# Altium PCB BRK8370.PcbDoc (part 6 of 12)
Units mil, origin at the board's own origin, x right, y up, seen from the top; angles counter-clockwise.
Board outline 8267.72 x 5708.66 mil, 6 copper layers (L1-TOP, L2-GND, L3-PWR, L4-PWR, L5-GND, L6-BOT), stack 68.606 mil thick; 319 components, 516 nets, 2008 pads, 1743 vias.
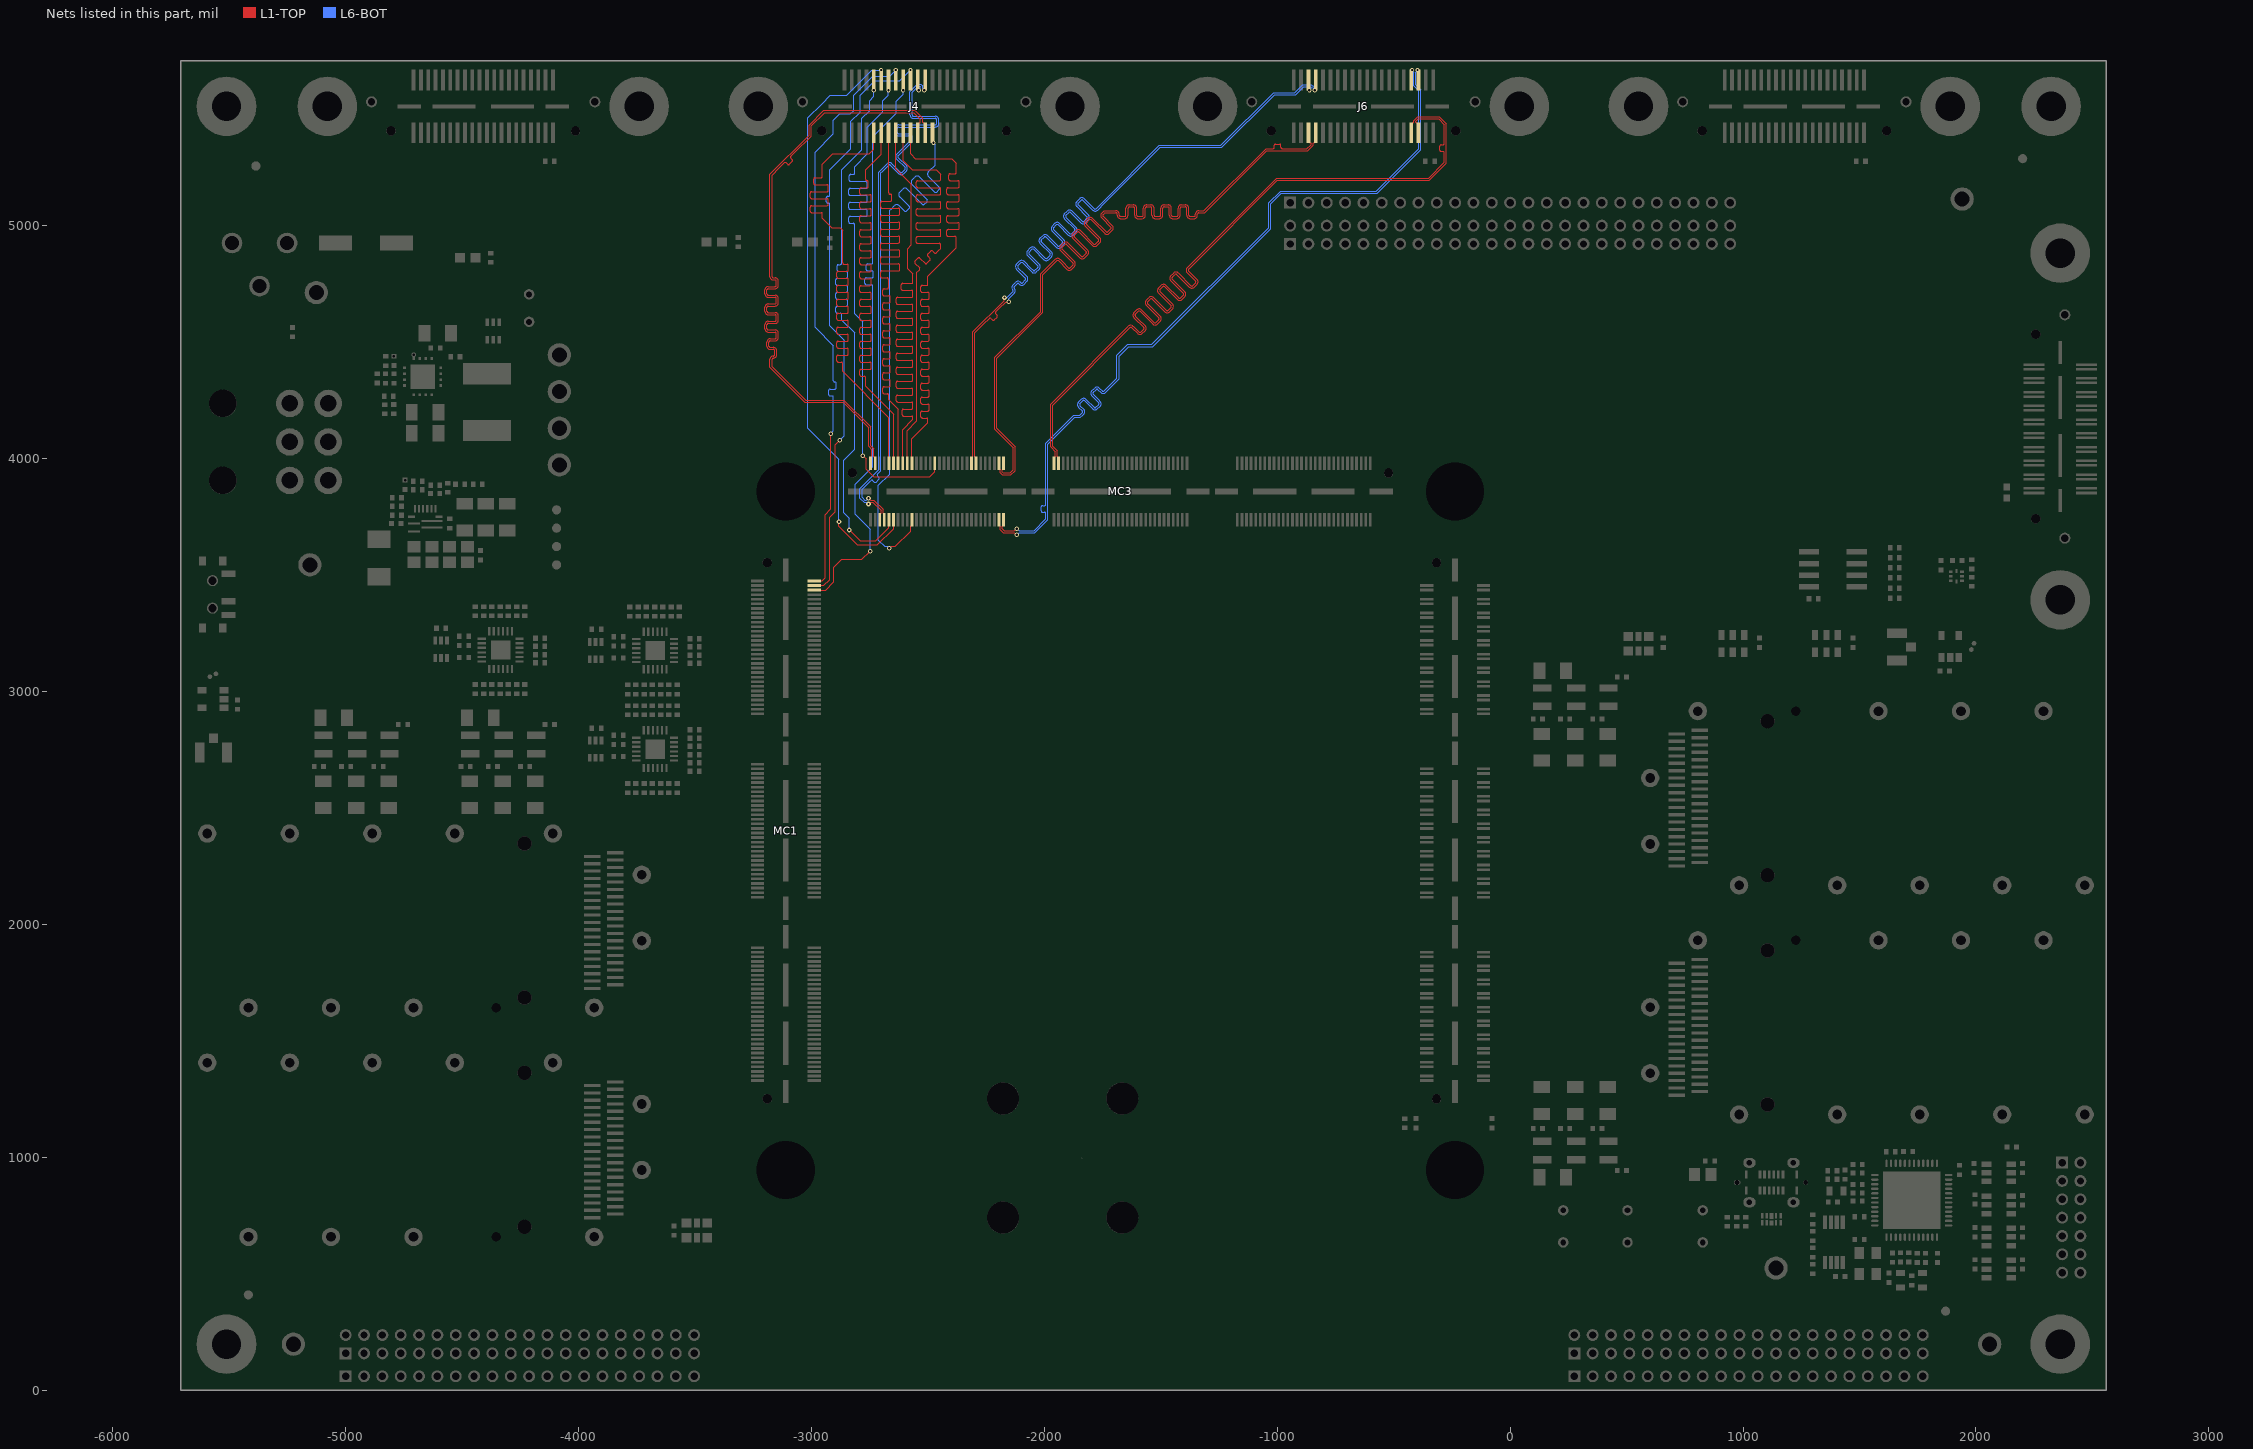
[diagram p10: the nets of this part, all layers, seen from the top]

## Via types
v1: diameter 20, hole 10, L1-TOP to L6-BOT, tented both sides, 957 vias
v2: diameter 18, hole 10, L1-TOP to L6-BOT, tented both sides, 786 vias

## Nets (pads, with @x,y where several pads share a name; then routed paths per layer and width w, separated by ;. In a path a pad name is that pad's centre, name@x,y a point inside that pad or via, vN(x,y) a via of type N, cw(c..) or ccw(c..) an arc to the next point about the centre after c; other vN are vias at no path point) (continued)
PORTB_S11_D5_N: J4.16 MC3.20 | length 2544.6
  L1-TOP w3.3: v1(-2665.35,3614.17) -2663.07,3614.17 -2655.07,3622.17 -2639.71,3622.17 -2574.24,3687.64 -2574.24,3708.63 -2568.9,3713.98 MC3.20@-2568.9,3736.61
  L6-BOT w3.3: v1(-2665.35,3614.17) -2667.64,3614.17 -2675.64,3622.17 -2686.15,3622.17 -2712.65,3648.68 -2712.65,3884.18 -2664.23,3932.6 -2664.23,5065.03 -2655.97,5073.29 -2643.89,5085.37 cw(c-2633.52,5075.01) -2623.16,5085.37 -2600.07,5062.29 ccw(c-2596.07,5066.29) -2592.07,5062.29 -2580.06,5074.3 ccw(c-2584.06,5078.3) -2580.06,5082.3 -2620.8,5123.04 cw(c-2610.46,5133.43) -2620.82,5143.8 -2608.78,5155.84 cw(c-2598.45,5145.44) -2589.6,5157.12 -2589.4,5157.12 -2523.63,5091.35 ccw(c-2519.64,5095.36) -2515.64,5091.36 -2503.63,5103.36 ccw(c-2507.63,5107.37) -2503.64,5111.38 ; -2503.66,5111.4 -2568.04,5175.78 cw(c-2557.71,5186.18) -2568.07,5196.55 -2556.03,5208.59 cw(c-2545.7,5198.19) -2536.85,5209.87 -2536.65,5209.87 -2470.88,5144.1 ccw(c-2466.89,5148.11) -2462.88,5144.11 -2450.88,5156.11 ccw(c-2454.88,5160.12) -2450.89,5164.13 ; v2(-2476.14,5355.65) -2476.14,5353.41 -2469.11,5346.37 -2469.11,5260.16 -2493.3,5235.97 -2497.65,5231.62 ccw(c-2487.28,5221.25) -2497.65,5210.89 -2450.91,5164.15
PORTB_S12_D6_P: J4.17 MC3.6 | length 2544.6
  L1-TOP w3.3: v1(-2754.97,3804.45) -2752.69,3804.45 -2744.69,3812.45 -2736.06,3812.45 -2701.35,3777.74 -2701.35,3764.59 -2706.69,3759.25 MC3.6@-2706.69,3736.61
  L6-BOT w3.3: v1(-2754.97,3804.45) -2757.26,3804.45 -2765.26,3812.45 -2774.25,3812.45 -2791.98,3830.19 -2791.98,3870.64 -2710.91,3951.71 -2710.91,5230.03 -2700.79,5240.16 -2675.23,5265.72 cw(c-2664.86,5255.35) -2654.49,5265.72 -2618.35,5229.58 ccw(c-2614.35,5233.58) -2610.35,5229.58 -2598.34,5241.58 ccw(c-2602.34,5245.58) -2598.34,5249.59 -2634.48,5285.73 cw(c-2624.12,5296.1) -2634.48,5306.46 -2630.13,5310.81 -2580.1,5360.84 -2577.05,5363.89 -2577.05,5380.4 ccw(c-2582.71,5380.4) -2582.71,5386.06 -2626.23,5386.06 cw(c-2626.23,5400.72) -2640.89,5400.72 -2640.89,5417.7 cw(c-2626.23,5417.7) -2626.23,5432.36 -2468.21,5432.36 ccw(c-2468.21,5438.02) -2462.55,5438.02 -2462.55,5455 ccw(c-2468.21,5455) -2468.21,5460.66 -2562.39,5460.66 cw(c-2562.39,5475.32) -2577.05,5475.32 -2577.05,5481.47 -2577.05,5575.8 -2545.57,5607.28 -2530.31,5607.28 -2523.11,5600.08 -2523.11,5590.54 -2516.07,5583.5 v2(-2516.07,5581.25)
PORTB_S13_D7_P: J4.18 MC3.1 | length 2726.1
  L1-TOP w3.3: MC3.1@-2746.06,3979.92 -2746.06,4002.56 -2740.72,4007.9 -2740.72,4037.59 -2754.95,4051.82 -2754.95,4131.96 -2864.37,4241.39 -3028.79,4241.39 -3177.17,4389.76 -3178.29,4390.89 -3178.29,4425.23 cw(c-3163.63,4425.23) -3163.63,4439.89 ccw(c-3163.63,4445.55) -3157.97,4445.55 -3157.97,4462.53 ccw(c-3163.63,4462.53) -3163.63,4468.19 -3176.83,4468.19 cw(c-3176.83,4482.85) -3191.49,4482.85 -3191.49,4499.83 cw(c-3176.83,4499.83) -3176.83,4514.49 -3156.51,4514.49 ccw(c-3156.51,4520.15) -3150.85,4520.15 -3150.85,4537.13 ccw(c-3156.51,4537.13) -3156.51,4542.79 -3185.39,4542.79 cw(c-3185.39,4557.45) -3200.05,4557.45 -3200.05,4574.43 cw(c-3185.39,4574.43) -3185.39,4589.09 -3156.51,4589.09 ccw(c-3156.51,4594.75) -3150.85,4594.75 -3150.85,4611.73 ccw(c-3156.51,4611.73) -3156.51,4617.39 -3185.39,4617.39 cw(c-3185.39,4632.05) -3200.05,4632.05 -3200.05,4649.03 cw(c-3185.39,4649.03) -3185.39,4663.69 -3156.51,4663.69 ccw(c-3156.51,4669.35) -3150.85,4669.35 -3150.85,4686.33 ccw(c-3156.51,4686.33) -3156.51,4691.99 -3185.39,4691.99 cw(c-3185.39,4706.65) -3200.05,4706.65 -3200.05,4723.63 cw(c-3185.39,4723.63) -3185.39,4738.29 -3156.51,4738.29 ccw(c-3156.51,4743.95) -3150.85,4743.95 -3150.85,4760.93 ccw(c-3156.51,4760.93) -3156.51,4766.59 -3163.63,4766.59 cw(c-3163.63,4781.25) -3178.29,4781.25 -3178.29,4787.4 -3178.29,5220.26 -3010.12,5388.43 -3010.12,5431.41 -2947.15,5494.38 -2556.5,5494.38 -2523.01,5460.89 -2523.01,5444.04 -2521.07,5442.11 -2518.11,5442.11 -2511.76,5435.76 J4.18@-2511.76,5399.01
PORTB_S14_D6_N: J4.19 MC3.8 | length 2544.6
  L1-TOP w3.3: v1(-2754.97,3829.45) -2752.69,3829.45 -2744.69,3821.45 -2732.33,3821.45 -2692.35,3781.47 -2692.35,3764.59 -2687.01,3759.25 MC3.8@-2687.01,3736.61
  L6-BOT w3.3: v1(-2754.97,3829.45) -2757.26,3829.45 -2765.26,3821.45 -2770.52,3821.45 -2782.98,3833.92 -2782.98,3866.91 -2766.1,3883.79 -2744.93,3904.96 cw(c-2740.92,3900.96) -2736.92,3904.96 -2730.94,3898.98 ccw(c-2726.94,3902.98) -2722.94,3898.98 -2710.93,3910.99 ccw(c-2714.93,3914.99) -2710.93,3918.99 -2716.91,3924.98 cw(c-2712.91,3928.98) -2716.91,3932.98 -2710.87,3939.02 -2701.91,3947.98 -2701.91,5226.3 -2694.42,5233.79 -2668.86,5259.35 cw(c-2664.86,5255.35) -2660.86,5259.35 -2624.71,5223.21 ccw(c-2614.35,5233.58) -2603.98,5223.21 -2591.94,5235.26 ccw(c-2602.34,5245.58) -2591.98,5255.95 -2628.12,5292.09 cw(c-2624.12,5296.1) -2628.12,5300.1 -2623.77,5304.45 -2568.05,5360.16 -2568.05,5360.84 -2568.05,5380.4 ccw(c-2582.71,5380.4) -2582.71,5395.06 -2626.23,5395.06 cw(c-2626.23,5400.72) -2631.89,5400.72 -2631.89,5417.7 cw(c-2626.23,5417.7) -2626.23,5423.36 -2468.21,5423.36 ccw(c-2468.21,5438.02) -2453.55,5438.02 -2453.55,5455 ccw(c-2468.21,5455) -2468.21,5469.66 -2562.39,5469.66 cw(c-2562.39,5475.32) -2568.05,5475.32 -2568.05,5481.47 -2568.05,5572.07 -2541.84,5598.28 -2534.04,5598.28 -2532.11,5596.35 -2532.11,5590.54 -2539.14,5583.5 v2(-2539.14,5581.25)
PORTB_S15_D7_N: J4.20 MC3.3 | length 2726.1
  L1-TOP w3.3: MC3.3@-2726.38,3979.92 -2726.38,4002.56 -2731.72,4007.9 -2731.72,4041.32 -2745.95,4055.54 -2745.95,4135.69 -2860.65,4250.39 -3025.06,4250.39 -3164.44,4389.76 -3169.29,4394.62 -3169.29,4425.23 cw(c-3163.63,4425.23) -3163.63,4430.89 ccw(c-3163.63,4445.55) -3148.97,4445.55 -3148.97,4462.53 ccw(c-3163.63,4462.53) -3163.63,4477.19 -3176.83,4477.19 cw(c-3176.83,4482.85) -3182.49,4482.85 -3182.49,4499.83 cw(c-3176.83,4499.83) -3176.83,4505.49 -3156.51,4505.49 ccw(c-3156.51,4520.15) -3141.85,4520.15 -3141.85,4537.13 ccw(c-3156.51,4537.13) -3156.51,4551.79 -3185.39,4551.79 cw(c-3185.39,4557.45) -3191.05,4557.45 -3191.05,4574.43 cw(c-3185.39,4574.43) -3185.39,4580.09 -3156.51,4580.09 ccw(c-3156.51,4594.75) -3141.85,4594.75 -3141.85,4611.73 ccw(c-3156.51,4611.73) -3156.51,4626.39 -3185.39,4626.39 cw(c-3185.39,4632.05) -3191.05,4632.05 -3191.05,4649.03 cw(c-3185.39,4649.03) -3185.39,4654.69 -3156.51,4654.69 ccw(c-3156.51,4669.35) -3141.85,4669.35 -3141.85,4686.33 ccw(c-3156.51,4686.33) -3156.51,4700.99 -3185.39,4700.99 cw(c-3185.39,4706.65) -3191.05,4706.65 -3191.05,4723.63 cw(c-3185.39,4723.63) -3185.39,4729.29 -3156.51,4729.29 ccw(c-3156.51,4743.95) -3141.85,4743.95 -3141.85,4760.93 ccw(c-3156.51,4760.93) -3156.51,4775.59 -3163.63,4775.59 cw(c-3163.63,4781.25) -3169.29,4781.25 -3169.29,4787.4 -3169.29,5216.54 -3137.8,5248.03 -3116.62,5269.21 cw(c-3112.62,5265.21) -3108.61,5269.21 -3102.64,5263.23 ccw(c-3098.64,5267.24) -3094.63,5263.23 -3082.63,5275.24 ccw(c-3086.63,5279.24) -3082.63,5283.25 -3088.6,5289.22 cw(c-3084.6,5293.22) -3088.6,5297.23 -3070.85,5314.98 -3001.12,5384.7 -3001.12,5427.68 -2943.43,5485.38 -2560.22,5485.38 -2532.01,5457.16 -2532.01,5444.04 -2533.94,5442.11 -2536.91,5442.11 -2543.26,5435.76 J4.20@-2543.26,5399.01
PORTB_S16: J4.21 MC1.178 | length 2543.1
  L1-TOP w4.96: MC1.178@-2988.58,3454.72 -2946.33,3454.72 -2921.18,3479.87 -2921.18,3747.91 -2897.64,3771.45 -2897.64,4059.06 v1(-2877.95,4078.74)
  L6-BOT w4.96: v1(-2877.95,4078.74) -2858.27,4098.43 -2858.27,4507.87 -2921.26,4570.87 -2921.26,5087.86 -2921.26,5090.34 ccw(c-2927.25,5090.34) -2927.25,5096.33 -2929.69,5096.33 cw(c-2929.69,5102.32) -2935.68,5102.32 -2935.68,5120.3 cw(c-2929.69,5120.3) -2929.69,5126.29 -2927.25,5126.29 ccw(c-2927.25,5132.29) -2921.26,5132.29 -2921.26,5213.47 -2921.26,5240.16 -2853.35,5308.07 -2830.71,5330.71 -2830.71,5448.08 -2791.34,5487.45 -2791.34,5559.06 -2728.35,5622.05 -2620.78,5622.05 v2(-2574.86,5667.97)
PORTB_S17: J4.22 MC3.19 | length 2720.9
  L1-TOP w4.96: J4.22@-2574.76,5399.01 -2574.76,5308.07 -2554.09,5287.4 -2397.64,5287.4 -2377.95,5267.72 -2377.95,5263.07 -2377.95,5229.01 cw(c-2383.95,5229.01) -2383.95,5223.01 -2404.38,5223.01 ccw(c-2404.38,5217.02) -2410.37,5217.02 -2410.37,5199.04 ccw(c-2404.38,5199.04) -2404.38,5193.05 -2371.04,5193.05 cw(c-2371.04,5187.06) -2365.05,5187.06 -2365.05,5169.08 cw(c-2371.04,5169.08) -2371.04,5163.09 -2413.03,5163.09 ccw(c-2413.03,5157.09) -2419.03,5157.09 -2419.03,5139.12 ccw(c-2413.03,5139.12) -2413.03,5133.12 -2371.04,5133.12 cw(c-2371.04,5127.13) -2365.05,5127.13 -2365.05,5109.15 cw(c-2371.04,5109.15) -2371.04,5103.16 -2413.03,5103.16 ccw(c-2413.03,5097.17) -2419.03,5097.17 -2419.03,5079.19 ccw(c-2413.03,5079.19) -2413.03,5073.2 -2371.04,5073.2 cw(c-2371.04,5067.2) -2365.05,5067.2 -2365.05,5049.23 cw(c-2371.04,5049.23) -2371.04,5043.23 -2413.03,5043.23 ccw(c-2413.03,5037.24) -2419.03,5037.24 -2419.03,5019.26 ccw(c-2413.03,5019.26) -2413.03,5013.27 -2371.04,5013.27 cw(c-2371.04,5007.28) -2365.05,5007.28 -2365.05,4989.3 cw(c-2371.04,4989.3) -2371.04,4983.31 -2413.03,4983.31 ccw(c-2413.03,4977.32) -2419.03,4977.32 -2419.03,4959.34 ccw(c-2413.03,4959.34) -2413.03,4953.35 -2383.95,4953.35 cw(c-2383.95,4947.35) -2377.95,4947.35 -2377.95,4944.87 -2377.95,4905.51 -2500,4783.46 -2500,4775.59 -2500,4749.12 cw(c-2505.99,4749.12) -2505.99,4743.13 -2524.29,4743.13 ccw(c-2524.29,4737.13) -2530.28,4737.13 -2530.28,4719.16 ccw(c-2524.29,4719.16) -2524.29,4713.16 -2500.35,4713.16 cw(c-2500.35,4707.17) -2494.36,4707.17 -2494.36,4689.19 cw(c-2500.35,4689.19) -2500.35,4683.2 -2524.29,4683.2 ccw(c-2524.29,4677.21) -2530.28,4677.21 -2530.28,4659.23 ccw(c-2524.29,4659.23) -2524.29,4653.24 -2500.35,4653.24 cw(c-2500.35,4647.24) -2494.36,4647.24 -2494.36,4629.27 cw(c-2500.35,4629.27) -2500.35,4623.27 -2524.29,4623.27 ccw(c-2524.29,4617.28) -2530.28,4617.28 -2530.28,4599.3 ccw(c-2524.29,4599.3) -2524.29,4593.31 -2500.35,4593.31 cw(c-2500.35,4587.32) -2494.36,4587.32 -2494.36,4569.34 cw(c-2500.35,4569.34) -2500.35,4563.35 -2524.29,4563.35 ccw(c-2524.29,4557.36) -2530.28,4557.36 -2530.28,4539.38 ccw(c-2524.29,4539.38) -2524.29,4533.38 -2500.35,4533.38 cw(c-2500.35,4527.39) -2494.36,4527.39 -2494.36,4509.41 cw(c-2500.35,4509.41) -2500.35,4503.42 -2524.29,4503.42 ccw(c-2524.29,4497.43) -2530.28,4497.43 -2530.28,4479.45 ccw(c-2524.29,4479.45) -2524.29,4473.46 -2500.35,4473.46 cw(c-2500.35,4467.47) -2494.36,4467.47 -2494.36,4449.49 cw(c-2500.35,4449.49) -2500.35,4443.5 -2524.29,4443.5 ccw(c-2524.29,4437.5) -2530.28,4437.5 -2530.28,4419.53 ccw(c-2524.29,4419.53) -2524.29,4413.53 -2500.35,4413.53 cw(c-2500.35,4407.54) -2494.36,4407.54 -2494.36,4389.56 cw(c-2500.35,4389.56) -2500.35,4383.57 -2524.29,4383.57 ccw(c-2524.29,4377.58) -2530.28,4377.58 -2530.28,4359.6 ccw(c-2524.29,4359.6) -2524.29,4353.61 -2500.35,4353.61 cw(c-2500.35,4347.61) -2494.36,4347.61 -2494.36,4329.64 cw(c-2500.35,4329.64) -2500.35,4323.64 -2524.29,4323.64 ccw(c-2524.29,4317.65) -2530.28,4317.65 -2530.28,4299.67 ccw(c-2524.29,4299.67) -2524.29,4293.68 -2500.35,4293.68 cw(c-2500.35,4287.69) -2494.36,4287.69 -2494.36,4269.71 cw(c-2500.35,4269.71) -2500.35,4263.72 -2524.29,4263.72 ccw(c-2524.29,4257.73) -2530.28,4257.73 -2530.28,4239.75 ccw(c-2524.29,4239.75) -2524.29,4233.75 -2500.35,4233.75 cw(c-2500.35,4227.76) -2494.36,4227.76 -2494.36,4209.78 cw(c-2500.35,4209.78) -2500.35,4203.79 -2524.29,4203.79 ccw(c-2524.29,4197.8) -2530.28,4197.8 -2530.28,4179.82 ccw(c-2524.29,4179.82) -2524.29,4173.83 -2505.99,4173.83 cw(c-2505.99,4167.84) -2500,4167.84 -2500,4165.35 -2500,4153.54 -2568.9,4084.65 MC3.19@-2568.9,3979.92
PORTB_S18: J4.23 MC1.176 | length 2543.1
  L1-TOP w4.96: MC1.176@-2988.58,3435.04 -2939.64,3435.04 -2904.22,3470.46 -2904.22,3532.79 -2870.08,3566.93 -2783.46,3566.93 v1(-2748.03,3602.36)
  L6-BOT w4.96: v1(-2748.03,3602.36) -2748.03,3696.85 -2811.02,3759.84 -2811.02,3889.76 -2736.22,3964.57 -2736.22,4736.99 -2736.22,4739.47 ccw(c-2742.21,4739.47) -2742.21,4745.47 -2764.43,4745.47 cw(c-2764.43,4751.46) -2770.42,4751.46 -2770.42,4769.44 cw(c-2764.43,4769.44) -2764.43,4775.43 -2740.83,4775.43 ccw(c-2740.83,4781.42) -2734.84,4781.42 -2734.84,4799.4 ccw(c-2740.83,4799.4) -2740.83,4805.39 -2758.42,4805.39 cw(c-2758.42,4811.39) -2764.41,4811.39 -2764.41,4829.36 cw(c-2758.42,4829.36) -2758.42,4835.36 -2742.21,4835.36 ccw(c-2742.21,4841.35) -2736.22,4841.35 -2736.22,4872.32 -2736.22,5381.89 -2635.31,5482.8 -2635.31,5533.98 -2606.36,5562.94 v2(-2606.36,5581.25)
PORTB_S19: J4.24 MC3.17 | length 2720.9
  L1-TOP w4.96: J4.24@-2606.26,5399.01 -2606.26,5279.48 -2566.93,5240.16 -2464.57,5240.16 -2444.88,5220.47 -2444.88,5215.83 -2444.88,5198.9 cw(c-2450.87,5198.9) -2450.87,5192.91 -2543.6,5192.91 ccw(c-2543.6,5186.91) -2549.6,5186.91 -2549.6,5168.94 ccw(c-2543.6,5168.94) -2543.6,5162.94 -2449.93,5162.94 cw(c-2449.93,5156.95) -2443.94,5156.95 -2443.94,5138.97 cw(c-2449.93,5138.97) -2449.93,5132.98 -2543.6,5132.98 ccw(c-2543.6,5126.99) -2549.6,5126.99 -2549.6,5109.01 ccw(c-2543.6,5109.01) -2543.6,5103.02 -2449.93,5103.02 cw(c-2449.93,5097.03) -2443.94,5097.03 -2443.94,5079.05 cw(c-2449.93,5079.05) -2449.93,5073.06 -2543.6,5073.06 ccw(c-2543.6,5067.06) -2549.6,5067.06 -2549.6,5049.09 ccw(c-2543.6,5049.09) -2543.6,5043.09 -2449.93,5043.09 cw(c-2449.93,5037.1) -2443.94,5037.1 -2443.94,5019.12 cw(c-2449.93,5019.12) -2449.93,5013.13 -2543.6,5013.13 ccw(c-2543.6,5007.14) -2549.6,5007.14 -2549.6,4989.16 ccw(c-2543.6,4989.16) -2543.6,4983.17 -2449.93,4983.17 cw(c-2449.93,4977.17) -2443.94,4977.17 -2443.94,4959.2 cw(c-2449.93,4959.2) -2449.93,4953.2 -2543.6,4953.2 ccw(c-2543.6,4947.21) -2549.6,4947.21 -2549.6,4929.23 ccw(c-2543.6,4929.23) -2543.6,4923.24 -2450.87,4923.24 cw(c-2450.87,4917.25) -2444.88,4917.25 -2444.88,4914.77 -2444.88,4901.57 -2451.13,4895.33 -2463.82,4882.63 cw(c-2468.06,4886.87) -2472.3,4882.63 -2480.32,4890.66 ccw(c-2484.56,4886.42) -2488.8,4890.66 -2501.51,4877.94 ccw(c-2497.27,4873.71) -2501.51,4869.47 -2491.28,4859.24 cw(c-2495.52,4855) -2491.28,4850.77 -2503.99,4838.05 cw(c-2508.23,4842.29) -2512.47,4838.05 -2534.44,4860.02 ccw(c-2538.67,4855.78) -2542.91,4860.02 -2555.62,4847.31 ccw(c-2551.39,4843.07) -2555.62,4838.83 -2535.86,4819.07 cw(c-2540.1,4814.83) -2535.86,4810.6 -2537.62,4808.84 -2547.24,4799.21 -2547.24,4161.42 -2588.58,4120.08 MC3.17@-2588.58,3979.92
PORTB_S20: J4.25 MC1.180 | length 2543.1
  L1-TOP w4.96: MC1.180@-2988.58,3474.41 -2954.72,3474.41 -2941.75,3487.39 -2941.75,3759.04 -2917.32,3783.46 v1(-2917.32,4106.3)
  L6-BOT w4.96: v1(-2917.32,4106.3) -2905.51,4118.11 -2905.51,4259.84 -2905.51,4262.32 ccw(c-2911.5,4262.32) -2911.5,4268.32 -2920.42,4268.32 cw(c-2920.42,4274.31) -2926.41,4274.31 -2926.41,4292.29 cw(c-2920.42,4292.29) -2920.42,4298.28 -2899.52,4298.28 ccw(c-2899.52,4304.27) -2893.53,4304.27 -2893.53,4322.25 ccw(c-2899.52,4322.25) -2899.52,4328.24 cw(c-2899.52,4334.24) -2905.51,4334.24 -2905.51,4381.89 -2905.51,4484.25 -2984.25,4562.99 -2984.25,5314.96 -2905.51,5393.7 -2905.51,5452.76 -2877.95,5480.32 -2832.74,5480.32 -2818.9,5494.16 -2818.9,5559.28 -2736.45,5641.73 -2664.09,5641.73 v2(-2637.86,5667.97)
PORTB_S21: J4.26 MC3.15 | length 2720.9
  L1-TOP w4.96: J4.26@-2637.76,5399.01 -2637.76,5244.05 -2570.87,5177.17 -2570.87,4917.32 -2586.61,4901.57 -2586.61,4814.96 -2564.21,4792.55 -2564.21,4784.85 -2564.21,4757.68 cw(c-2570.2,4757.68) -2570.2,4751.69 -2607.81,4751.69 ccw(c-2607.81,4745.7) -2613.8,4745.7 -2613.8,4727.72 ccw(c-2607.81,4727.72) -2607.81,4721.73 -2570.2,4721.73 cw(c-2570.2,4715.73) -2564.21,4715.73 -2564.21,4697.75 cw(c-2570.2,4697.75) -2570.2,4691.76 -2630.16,4691.76 ccw(c-2630.16,4685.77) -2636.16,4685.77 -2636.16,4667.79 ccw(c-2630.16,4667.79) -2630.16,4661.8 -2570.2,4661.8 cw(c-2570.2,4655.81) -2564.21,4655.81 -2564.21,4637.83 cw(c-2570.2,4637.83) -2570.2,4631.84 -2630.16,4631.84 ccw(c-2630.16,4625.84) -2636.16,4625.84 -2636.16,4607.87 ccw(c-2630.16,4607.87) -2630.16,4601.87 -2570.2,4601.87 cw(c-2570.2,4595.88) -2564.21,4595.88 -2564.21,4577.9 cw(c-2570.2,4577.9) -2570.2,4571.91 -2630.16,4571.91 ccw(c-2630.16,4565.92) -2636.16,4565.92 -2636.16,4547.94 ccw(c-2630.16,4547.94) -2630.16,4541.95 -2570.2,4541.95 cw(c-2570.2,4535.95) -2564.21,4535.95 -2564.21,4517.98 cw(c-2570.2,4517.98) -2570.2,4511.98 -2630.16,4511.98 ccw(c-2630.16,4505.99) -2636.16,4505.99 -2636.16,4488.01 ccw(c-2630.16,4488.01) -2630.16,4482.02 -2570.2,4482.02 cw(c-2570.2,4476.03) -2564.21,4476.03 -2564.21,4458.05 cw(c-2570.2,4458.05) -2570.2,4452.06 -2630.16,4452.06 ccw(c-2630.16,4446.07) -2636.16,4446.07 -2636.16,4428.09 ccw(c-2630.16,4428.09) -2630.16,4422.1 -2570.2,4422.1 cw(c-2570.2,4416.1) -2564.21,4416.1 -2564.21,4398.12 cw(c-2570.2,4398.12) -2570.2,4392.13 -2630.16,4392.13 ccw(c-2630.16,4386.14) -2636.16,4386.14 -2636.16,4368.16 ccw(c-2630.16,4368.16) -2630.16,4362.17 -2570.2,4362.17 cw(c-2570.2,4356.18) -2564.21,4356.18 -2564.21,4338.2 cw(c-2570.2,4338.2) -2570.2,4332.21 -2630.16,4332.21 ccw(c-2630.16,4326.21) -2636.16,4326.21 -2636.16,4308.24 ccw(c-2630.16,4308.24) -2630.16,4302.24 -2570.2,4302.24 cw(c-2570.2,4296.25) -2564.21,4296.25 -2564.21,4278.27 cw(c-2570.2,4278.27) -2570.2,4272.28 -2629.66,4272.28 ccw(c-2629.66,4266.29) -2635.65,4266.29 -2635.65,4248.31 ccw(c-2629.66,4248.31) -2629.66,4242.32 -2570.2,4242.32 cw(c-2570.2,4236.32) -2564.21,4236.32 -2564.21,4218.35 cw(c-2570.2,4218.35) -2570.2,4212.35 -2605,4212.35 ccw(c-2605,4206.36) -2610.99,4206.36 -2610.99,4188.38 ccw(c-2605,4188.38) -2605,4182.39 -2570.2,4182.39 cw(c-2570.2,4176.4) -2564.21,4176.4 -2564.21,4173.92 -2564.21,4168.44 -2608.27,4124.38 MC3.15@-2608.27,3979.92
PORTB_S22: J4.27 MC3.29 | length 2543.1
  L1-TOP w4.96: v1(-2779.53,4011.81) -2765.86,3998.14 -2765.86,3954.69 -2732.43,3921.26 -2492.13,3921.26 -2470.47,3942.91 MC3.29@-2470.47,3979.92
  L6-BOT w4.96: v1(-2779.53,4011.81) -2779.53,4586.61 -2814.96,4622.05 -2814.96,5001.31 -2814.96,5003.79 ccw(c-2820.95,5003.79) -2820.95,5009.78 -2833.97,5009.78 cw(c-2833.97,5015.77) -2839.96,5015.77 -2839.96,5033.75 cw(c-2833.97,5033.75) -2833.97,5039.74 -2766.51,5039.74 ccw(c-2766.51,5045.74) -2760.51,5045.74 -2760.51,5063.71 ccw(c-2766.51,5063.71) -2766.51,5069.71 -2833.97,5069.71 cw(c-2833.97,5075.7) -2839.96,5075.7 -2839.96,5093.68 cw(c-2833.97,5093.68) -2833.97,5099.67 -2766.51,5099.67 ccw(c-2766.51,5105.66) -2760.51,5105.66 -2760.51,5123.64 ccw(c-2766.51,5123.64) -2766.51,5129.63 -2833.97,5129.63 cw(c-2833.97,5135.63) -2839.96,5135.63 -2839.96,5153.6 cw(c-2833.97,5153.6) -2833.97,5159.6 -2766.51,5159.6 ccw(c-2766.51,5165.59) -2760.51,5165.59 -2760.51,5183.57 ccw(c-2766.51,5183.57) -2766.51,5189.56 -2831.55,5189.56 cw(c-2831.55,5195.55) -2837.54,5195.55 -2837.54,5213.53 cw(c-2831.55,5213.53) -2831.55,5219.52 -2820.95,5219.52 ccw(c-2820.95,5225.51) -2814.96,5225.51 -2814.96,5243.16 -2814.96,5252.95 -2759.84,5308.07 -2759.84,5421.26 -2692.91,5488.19 -2692.91,5535.2 -2669.36,5558.76 v2(-2669.36,5581.25)
PORTB_S23: J4.28 MC3.13 | length 2720.9
  L1-TOP w4.96: J4.28@-2669.26,5399.01 -2669.26,5171.78 -2669.26,5140.97 ccw(c-2663.26,5140.97) -2663.26,5134.98 -2661.14,5134.98 cw(c-2661.14,5128.99) -2655.14,5128.99 -2655.14,5111.01 cw(c-2661.14,5111.01) -2661.14,5105.02 -2697.52,5105.02 ccw(c-2697.52,5099.03) -2703.51,5099.03 -2703.51,5081.05 ccw(c-2697.52,5081.05) -2697.52,5075.06 -2626.59,5075.06 cw(c-2626.59,5069.06) -2620.6,5069.06 -2620.6,5051.09 cw(c-2626.59,5051.09) -2626.59,5045.09 -2697.52,5045.09 ccw(c-2697.52,5039.1) -2703.51,5039.1 -2703.51,5021.12 ccw(c-2697.52,5021.12) -2697.52,5015.13 -2626.59,5015.13 cw(c-2626.59,5009.14) -2620.6,5009.14 -2620.6,4991.16 cw(c-2626.59,4991.16) -2626.59,4985.17 -2697.52,4985.17 ccw(c-2697.52,4979.17) -2703.51,4979.17 -2703.51,4961.2 ccw(c-2697.52,4961.2) -2697.52,4955.2 -2626.59,4955.2 cw(c-2626.59,4949.21) -2620.6,4949.21 -2620.6,4931.23 cw(c-2626.59,4931.23) -2626.59,4925.24 -2697.52,4925.24 ccw(c-2697.52,4919.25) -2703.51,4919.25 -2703.51,4901.27 ccw(c-2697.52,4901.27) -2697.52,4895.28 -2626.59,4895.28 cw(c-2626.59,4889.28) -2620.6,4889.28 -2620.6,4871.31 cw(c-2626.59,4871.31) -2626.59,4865.31 -2697.52,4865.31 ccw(c-2697.52,4859.32) -2703.51,4859.32 -2703.51,4841.34 ccw(c-2697.52,4841.34) -2697.52,4835.35 -2626.59,4835.35 cw(c-2626.59,4829.36) -2620.6,4829.36 -2620.6,4811.38 cw(c-2626.59,4811.38) -2626.59,4805.39 -2697.52,4805.39 ccw(c-2697.52,4799.4) -2703.51,4799.4 -2703.51,4781.42 ccw(c-2697.52,4781.42) -2697.52,4775.43 -2675.25,4775.43 cw(c-2675.25,4769.43) -2669.26,4769.43 -2669.26,4766.95 -2669.26,4746.64 -2669.26,4734.09 cw(c-2675.25,4734.09) -2675.25,4728.1 -2688.26,4728.1 ccw(c-2688.26,4722.11) -2694.26,4722.11 -2694.26,4704.13 ccw(c-2688.26,4704.13) -2688.26,4698.14 -2667.53,4698.14 cw(c-2667.53,4692.14) -2661.54,4692.14 -2661.54,4674.17 cw(c-2667.53,4674.17) -2667.53,4668.17 -2688.26,4668.17 ccw(c-2688.26,4662.18) -2694.26,4662.18 -2694.26,4644.2 ccw(c-2688.26,4644.2) -2688.26,4638.21 -2667.53,4638.21 cw(c-2667.53,4632.22) -2661.54,4632.22 -2661.54,4614.24 cw(c-2667.53,4614.24) -2667.53,4608.25 -2688.26,4608.25 ccw(c-2688.26,4602.26) -2694.26,4602.26 -2694.26,4584.28 ccw(c-2688.26,4584.28) -2688.26,4578.29 -2667.53,4578.29 cw(c-2667.53,4572.29) -2661.54,4572.29 -2661.54,4554.31 cw(c-2667.53,4554.31) -2667.53,4548.32 -2688.26,4548.32 ccw(c-2688.26,4542.33) -2694.26,4542.33 -2694.26,4524.35 ccw(c-2688.26,4524.35) -2688.26,4518.36 -2667.53,4518.36 cw(c-2667.53,4512.37) -2661.54,4512.37 -2661.54,4494.39 cw(c-2667.53,4494.39) -2667.53,4488.4 -2688.26,4488.4 ccw(c-2688.26,4482.4) -2694.26,4482.4 -2694.26,4464.43 ccw(c-2688.26,4464.43) -2688.26,4458.43 -2667.53,4458.43 cw(c-2667.53,4452.44) -2661.54,4452.44 -2661.54,4434.46 cw(c-2667.53,4434.46) -2667.53,4428.47 -2688.26,4428.47 ccw(c-2688.26,4422.48) -2694.26,4422.48 -2694.26,4404.5 ccw(c-2688.26,4404.5) -2688.26,4398.51 -2667.53,4398.51 cw(c-2667.53,4392.51) -2661.54,4392.51 -2661.54,4374.54 cw(c-2667.53,4374.54) -2667.53,4368.54 -2688.26,4368.54 ccw(c-2688.26,4362.55) -2694.26,4362.55 -2694.26,4344.57 ccw(c-2688.26,4344.57) -2688.26,4338.58 -2667.53,4338.58 cw(c-2667.53,4332.59) -2661.54,4332.59 -2661.54,4314.61 cw(c-2667.53,4314.61) -2667.53,4308.62 -2688.26,4308.62 ccw(c-2688.26,4302.63) -2694.26,4302.63 -2694.26,4284.65 ccw(c-2688.26,4284.65) -2688.26,4278.66 -2675.25,4278.66 cw(c-2675.25,4272.66) -2669.26,4272.66 -2669.26,4270.18 -2669.26,4251.93 -2627.95,4210.63 MC3.13@-2627.95,3979.92
PORTB_S24: J4.29 MC3.12 | length 2542.3
  L1-TOP w4.96: v1(-2881.89,3728.35) -2881.89,3708.66 -2803.15,3629.92 -2716.54,3629.92 -2647.64,3698.82 MC3.12@-2647.64,3736.61
  L6-BOT w4.96: v1(-2881.89,3728.35) -2881.89,3996.06 -3015.75,4129.92 -3015.75,5462.13 -2954.72,5523.15 -2918.82,5559.06 -2848.62,5559.06 -2740.88,5666.8 -2702.03,5666.8 v2(-2700.86,5667.97)
PORTB_S25: J4.30 MC3.11 | length 2720.9
  L1-TOP w4.96: J4.30@-2700.76,5399.01 -2700.76,5307.12 -2767.72,5240.16 -2767.72,5229.08 -2767.72,5198.22 ccw(c-2761.72,5198.22) -2761.72,5192.23 cw(c-2761.72,5186.23) -2755.73,5186.23 -2755.73,5168.26 cw(c-2761.72,5168.26) -2761.72,5162.26 -2786.49,5162.26 ccw(c-2786.49,5156.27) -2792.48,5156.27 -2792.48,5138.29 ccw(c-2786.49,5138.29) -2786.49,5132.3 -2748.71,5132.3 cw(c-2748.71,5126.31) -2742.72,5126.31 -2742.72,5108.33 cw(c-2748.71,5108.33) -2748.71,5102.34 -2786.72,5102.34 ccw(c-2786.72,5096.34) -2792.72,5096.34 -2792.72,5078.37 ccw(c-2786.72,5078.37) -2786.72,5072.37 -2748.71,5072.37 cw(c-2748.71,5066.38) -2742.72,5066.38 -2742.72,5048.4 cw(c-2748.71,5048.4) -2748.71,5042.41 -2786.72,5042.41 ccw(c-2786.72,5036.42) -2792.72,5036.42 -2792.72,5018.44 ccw(c-2786.72,5018.44) -2786.72,5012.45 -2748.71,5012.45 cw(c-2748.71,5006.46) -2742.72,5006.46 -2742.72,4988.48 cw(c-2748.71,4988.48) -2748.71,4982.49 -2786.72,4982.49 ccw(c-2786.72,4976.49) -2792.72,4976.49 -2792.72,4958.51 ccw(c-2786.72,4958.51) -2786.72,4952.52 -2748.71,4952.52 cw(c-2748.71,4946.53) -2742.72,4946.53 -2742.72,4928.55 cw(c-2748.71,4928.55) -2748.71,4922.56 -2786.72,4922.56 ccw(c-2786.72,4916.57) -2792.72,4916.57 -2792.72,4898.59 ccw(c-2786.72,4898.59) -2786.72,4892.6 -2748.71,4892.6 cw(c-2748.71,4886.6) -2742.72,4886.6 -2742.72,4868.63 cw(c-2748.71,4868.63) -2748.71,4862.63 -2786.72,4862.63 ccw(c-2786.72,4856.64) -2792.72,4856.64 -2792.72,4838.66 ccw(c-2786.72,4838.66) -2786.72,4832.67 -2748.71,4832.67 cw(c-2748.71,4826.68) -2742.72,4826.68 -2742.72,4808.7 cw(c-2748.71,4808.7) -2748.71,4802.71 -2786.72,4802.71 ccw(c-2786.72,4796.71) -2792.72,4796.71 -2792.72,4778.74 ccw(c-2786.72,4778.74) -2786.72,4772.74 -2748.71,4772.74 cw(c-2748.71,4766.75) -2742.72,4766.75 -2742.72,4748.77 cw(c-2748.71,4748.77) -2748.71,4742.78 -2786.72,4742.78 ccw(c-2786.72,4736.79) -2792.72,4736.79 -2792.72,4718.81 ccw(c-2786.72,4718.81) -2786.72,4712.82 -2748.71,4712.82 cw(c-2748.71,4706.83) -2742.72,4706.83 -2742.72,4688.85 cw(c-2748.71,4688.85) -2748.71,4682.86 -2786.72,4682.86 ccw(c-2786.72,4676.86) -2792.72,4676.86 -2792.72,4658.88 ccw(c-2786.72,4658.88) -2786.72,4652.89 -2748.71,4652.89 cw(c-2748.71,4646.9) -2742.72,4646.9 -2742.72,4628.92 cw(c-2748.71,4628.92) -2748.71,4622.93 -2786.72,4622.93 ccw(c-2786.72,4616.94) -2792.72,4616.94 -2792.72,4598.96 ccw(c-2786.72,4598.96) -2786.72,4592.97 -2748.71,4592.97 cw(c-2748.71,4586.97) -2742.72,4586.97 -2742.72,4569 cw(c-2748.71,4569) -2748.71,4563 -2786.72,4563 ccw(c-2786.72,4557.01) -2792.72,4557.01 -2792.72,4539.03 ccw(c-2786.72,4539.03) -2786.72,4533.04 -2748.71,4533.04 cw(c-2748.71,4527.05) -2742.72,4527.05 -2742.72,4509.07 cw(c-2748.71,4509.07) -2748.71,4503.08 -2786.72,4503.08 ccw(c-2786.72,4497.08) -2792.72,4497.08 -2792.72,4479.11 ccw(c-2786.72,4479.11) -2786.72,4473.11 -2748.71,4473.11 cw(c-2748.71,4467.12) -2742.72,4467.12 -2742.72,4449.14 cw(c-2748.71,4449.14) -2748.71,4443.15 -2786.72,4443.15 ccw(c-2786.72,4437.16) -2792.72,4437.16 -2792.72,4419.18 ccw(c-2786.72,4419.18) -2786.72,4413.19 -2748.71,4413.19 cw(c-2748.71,4407.2) -2742.72,4407.2 -2742.72,4389.22 cw(c-2748.71,4389.22) -2748.71,4383.23 -2786.72,4383.23 ccw(c-2786.72,4377.23) -2792.72,4377.23 -2792.72,4359.25 ccw(c-2786.72,4359.25) -2786.72,4353.26 -2773.71,4353.26 cw(c-2773.71,4347.27) -2767.72,4347.27 -2767.72,4344.79 -2767.72,4311.02 -2647.64,4190.94 MC3.11@-2647.64,3979.92
PORTB_S26: J4.31 MC3.10 | length 2543.1
  L1-TOP w4.96: v1(-2837.42,3692.69) -2836.69,3692.69 -2790.89,3646.88 -2723.56,3646.88 -2667.32,3703.12 MC3.10@-2667.32,3736.61
  L6-BOT w4.96: v1(-2837.42,3692.69) -2837.42,3742.93 -2862.19,3767.7 -2862.19,3992.14 -2814.96,4039.37 -2814.96,4539.37 -2870.08,4594.49 -2870.08,4614.74 -2870.08,4617.22 ccw(c-2876.07,4617.22) -2876.07,4623.21 -2889.09,4623.21 cw(c-2889.09,4629.2) -2895.08,4629.2 -2895.08,4647.18 cw(c-2889.09,4647.18) -2889.09,4653.17 -2851.07,4653.17 ccw(c-2851.07,4659.17) -2845.08,4659.17 -2845.08,4677.15 ccw(c-2851.07,4677.15) -2851.07,4683.14 -2889.09,4683.14 cw(c-2889.09,4689.13) -2895.08,4689.13 -2895.08,4707.11 cw(c-2889.09,4707.11) -2889.09,4713.1 -2851.07,4713.1 ccw(c-2851.07,4719.09) -2845.08,4719.09 -2845.08,4737.07 ccw(c-2851.07,4737.07) -2851.07,4743.06 -2889.09,4743.06 cw(c-2889.09,4749.06) -2895.08,4749.06 -2895.08,4767.03 cw(c-2889.09,4767.03) -2889.09,4773.03 -2851.07,4773.03 ccw(c-2851.07,4779.02) -2845.08,4779.02 -2845.08,4797 ccw(c-2851.07,4797) -2851.07,4802.99 -2884.16,4802.99 cw(c-2884.16,4808.98) -2890.15,4808.98 -2890.15,4826.96 cw(c-2884.16,4826.96) -2884.16,4832.95 -2876.07,4832.95 ccw(c-2876.07,4838.95) -2870.08,4838.95 -2870.08,4874.02 -2870.08,5240.01 -2783.46,5326.63 -2783.46,5461.06 -2750.31,5494.22 -2750.31,5537.1 -2732.36,5555.05 v2(-2732.36,5581.25)
PORTB_S27: J4.32 MC3.9 | length 2720.9
  L1-TOP w4.96: J4.32@-2732.26,5399.01 -2732.26,5326.8 -2750.98,5308.07 -2908.46,5308.07 -2952.76,5263.78 -2952.76,5250.52 -2952.76,5211.67 cw(c-2958.75,5211.67) -2958.75,5205.68 -2985.14,5205.68 ccw(c-2985.14,5199.69) -2991.13,5199.69 -2991.13,5181.71 ccw(c-2985.14,5181.71) -2985.14,5175.72 -2933.75,5175.72 cw(c-2933.75,5169.73) -2927.76,5169.73 -2927.76,5151.75 cw(c-2933.75,5151.75) -2933.75,5145.76 -2999.28,5145.75 ccw(c-2999.28,5139.76) -3005.27,5139.76 -3005.27,5121.78 ccw(c-2999.28,5121.78) -2999.28,5115.79 -2933.75,5115.79 cw(c-2933.75,5109.8) -2927.76,5109.8 -2927.76,5091.82 cw(c-2933.75,5091.82) -2933.75,5085.83 -2999.28,5085.83 ccw(c-2999.28,5079.84) -3005.27,5079.84 -3005.27,5061.86 ccw(c-2999.28,5061.86) -2999.28,5055.87 -2958.75,5055.87 cw(c-2958.75,5049.87) -2952.76,5049.87 -2952.76,5047.39 -2952.76,5030.76 -2912,4990.01 -2875.83,4990.01 -2866.14,4980.31 -2866.14,4862.2 -2866.14,4839.46 ccw(c-2860.15,4839.46) -2860.15,4833.47 -2847.13,4833.47 cw(c-2847.13,4827.48) -2841.14,4827.48 -2841.14,4809.5 cw(c-2847.13,4809.5) -2847.13,4803.51 -2885.15,4803.51 ccw(c-2885.15,4797.51) -2891.14,4797.51 -2891.14,4779.53 ccw(c-2885.15,4779.53) -2885.15,4773.54 -2847.13,4773.54 cw(c-2847.13,4767.55) -2841.14,4767.55 -2841.14,4749.57 cw(c-2847.13,4749.57) -2847.13,4743.58 -2885.15,4743.58 ccw(c-2885.15,4737.59) -2891.14,4737.59 -2891.14,4719.61 ccw(c-2885.15,4719.61) -2885.15,4713.62 -2847.13,4713.62 cw(c-2847.13,4707.62) -2841.14,4707.62 -2841.14,4689.65 cw(c-2847.13,4689.65) -2847.13,4683.65 -2885.15,4683.65 ccw(c-2885.15,4677.66) -2891.14,4677.66 -2891.14,4659.68 ccw(c-2885.15,4659.68) -2885.15,4653.69 -2847.13,4653.69 cw(c-2847.13,4647.7) -2841.14,4647.7 -2841.14,4629.72 cw(c-2847.13,4629.72) -2847.13,4623.73 -2885.15,4623.73 ccw(c-2885.15,4617.73) -2891.14,4617.73 -2891.14,4599.76 ccw(c-2885.15,4599.76) -2885.15,4593.76 -2847.13,4593.76 cw(c-2847.13,4587.77) -2841.14,4587.77 -2841.14,4569.79 cw(c-2847.13,4569.79) -2847.13,4563.8 -2885.15,4563.8 ccw(c-2885.15,4557.81) -2891.14,4557.81 -2891.14,4539.83 ccw(c-2885.15,4539.83) -2885.15,4533.84 -2847.13,4533.84 cw(c-2847.13,4527.85) -2841.14,4527.85 -2841.14,4509.87 cw(c-2847.13,4509.87) -2847.13,4503.88 -2885.15,4503.88 ccw(c-2885.15,4497.88) -2891.14,4497.88 -2891.14,4479.91 ccw(c-2885.15,4479.91) -2885.15,4473.91 -2847.13,4473.91 cw(c-2847.13,4467.92) -2841.14,4467.92 -2841.14,4449.94 cw(c-2847.13,4449.94) -2847.13,4443.95 -2885.15,4443.95 ccw(c-2885.15,4437.96) -2891.14,4437.96 -2891.14,4419.98 ccw(c-2885.15,4419.98) -2885.15,4413.99 -2872.13,4413.99 cw(c-2872.13,4407.99) -2866.14,4407.99 -2866.14,4405.51 -2866.14,4374.07 -2667.32,4175.25 MC3.9@-2667.32,3979.92
PORTC_C2P_CLK_N: J6.36 MC3.59 | length 3566.9
  L1-TOP w3.3: MC3.59@-2175.2,3979.92 -2175.2,3957.28 -2180.54,3951.94 -2180.54,3941.41 -2177.25,3938.12 -2147.37,3938.12 -2133.81,3951.68 -2133.81,4046.28 -2212.86,4125.33 -2212.86,4433.72 -2015.75,4630.84 -2015.75,4792.26 -2006.36,4801.64 -1953.31,4854.69 cw(c-1942.94,4844.33) -1934.09,4856.01 -1933.89,4856.01 -1932.59,4854.71 -1921.7,4843.82 -1896.93,4819.05 ccw(c-1892.93,4823.05) -1888.93,4819.05 -1876.92,4831.05 ccw(c-1880.92,4835.06) -1876.92,4839.06 -1930.22,4892.36 cw(c-1919.88,4902.75) -1930.24,4913.12 -1918.2,4925.16 cw(c-1907.87,4914.76) -1899.02,4926.44 -1898.82,4926.44 -1840.62,4868.24 ccw(c-1836.62,4872.24) -1832.62,4868.24 -1820.61,4880.25 ccw(c-1824.61,4884.25) -1820.62,4888.26 -1877.46,4945.1 cw(c-1867.13,4955.5) -1877.49,4965.87 -1865.45,4977.91 cw(c-1855.12,4967.51) -1846.27,4979.19 -1846.07,4979.19 -1787.87,4920.99 ccw(c-1783.87,4924.99) -1779.87,4920.99 -1767.86,4933 ccw(c-1771.86,4937) -1767.87,4941.01 -1824.71,4997.85 cw(c-1814.38,5008.25) -1824.74,5018.62 -1812.7,5030.66 cw(c-1802.37,5020.26) -1793.52,5031.94 -1793.32,5031.94 -1735.12,4973.74 ccw(c-1731.12,4977.74) -1727.12,4973.74 -1715.11,4985.75 ccw(c-1719.11,4989.75) -1715.12,4993.76 -1754.32,5032.96 cw(c-1743.95,5043.32) -1754.32,5053.69 -1749.97,5058.04 -1743.89,5064.12 -1712.6,5064.12 -1692.81,5064.12 cw(c-1692.81,5049.46) -1678.15,5049.46 -1678.15,5044.78 ccw(c-1672.49,5044.78) -1672.49,5039.12 -1655.51,5039.12 ccw(c-1655.51,5044.78) -1649.85,5044.78 -1649.85,5074.46 cw(c-1635.19,5074.46) -1635.19,5089.12 -1618.21,5089.12 cw(c-1618.21,5074.46) -1603.55,5074.46 -1603.55,5044.78 ccw(c-1597.89,5044.78) -1597.89,5039.12 -1580.91,5039.12 ccw(c-1580.91,5044.78) -1575.25,5044.78 -1575.25,5074.46 cw(c-1560.59,5074.46) -1560.59,5089.12 -1543.61,5089.12 cw(c-1543.61,5074.46) -1528.95,5074.46 -1528.95,5044.78 ccw(c-1523.29,5044.78) -1523.29,5039.12 -1506.31,5039.12 ccw(c-1506.31,5044.78) -1500.65,5044.78 -1500.65,5074.46 cw(c-1485.99,5074.46) -1485.99,5089.12 -1469.01,5089.12 cw(c-1469.01,5074.46) -1454.35,5074.46 -1454.35,5044.78 ccw(c-1448.69,5044.78) -1448.69,5039.12 -1431.71,5039.12 ccw(c-1431.71,5044.78) -1426.05,5044.78 -1426.05,5074.46 cw(c-1411.39,5074.46) -1411.39,5089.12 -1394.41,5089.12 cw(c-1394.41,5074.46) -1379.75,5074.46 -1379.75,5044.78 ccw(c-1374.09,5044.78) -1374.09,5039.12 -1357.11,5039.12 ccw(c-1357.11,5044.78) -1351.45,5044.78 -1351.45,5049.46 cw(c-1336.79,5049.46) -1336.79,5064.12 -1330.64,5064.12 -1314.61,5064.12 -1048.18,5330.55 -1019.68,5330.55 -1018.03,5330.55 ccw(c-1018.03,5336.21) -1012.37,5336.21 -1012.37,5344.66 cw(c-1006.71,5344.66) -1006.71,5350.32 -989.73,5350.32 cw(c-989.73,5344.66) -984.07,5344.66 -984.07,5336.21 ccw(c-978.41,5336.21) -978.41,5330.55 -948.82,5330.55 -872.43,5330.55 -854.87,5348.11 -854.87,5353.98 -856.8,5355.91 -859.77,5355.91 -866.12,5362.26 J6.36@-866.12,5399.01
PORTC_C2P_CLK_P: J6.34 MC3.57 | length 3566.8
  L1-TOP w3.3: MC3.57@-2194.88,3979.92 -2194.88,3957.28 -2189.54,3951.94 -2189.54,3937.68 -2180.98,3929.12 -2143.65,3929.12 -2124.81,3947.95 -2124.81,4050.01 -2203.86,4129.06 -2203.86,4429.99 -2006.75,4627.11 -2006.75,4788.53 -2000,4795.28 -1946.94,4848.33 cw(c-1942.94,4844.33) -1938.92,4848.31 -1903.29,4812.68 ccw(c-1892.93,4823.05) -1882.56,4812.68 -1870.52,4824.73 ccw(c-1880.92,4835.06) -1870.55,4845.42 -1907.61,4882.48 -1923.88,4898.75 cw(c-1919.88,4902.75) -1923.88,4906.75 -1911.87,4918.76 cw(c-1907.87,4914.76) -1903.86,4918.75 ; -1903.84,4918.73 -1847.02,4861.91 ccw(c-1836.62,4872.24) -1826.25,4861.88 -1814.21,4873.92 ccw(c-1824.61,4884.25) -1812.93,4893.1 -1812.93,4893.3 -1871.13,4951.5 cw(c-1867.13,4955.5) -1871.13,4959.5 -1859.12,4971.51 cw(c-1855.12,4967.51) -1851.11,4971.5 ; -1851.09,4971.48 -1794.27,4914.66 ccw(c-1783.87,4924.99) -1773.5,4914.63 -1761.46,4926.67 ccw(c-1771.86,4937) -1760.18,4945.85 -1760.18,4946.05 -1818.38,5004.25 cw(c-1814.38,5008.25) -1818.38,5012.25 -1806.37,5024.26 cw(c-1802.37,5020.26) -1798.36,5024.25 ; -1798.34,5024.23 -1741.52,4967.41 ccw(c-1731.12,4977.74) -1720.75,4967.38 -1708.71,4979.42 ccw(c-1719.11,4989.75) -1707.43,4998.6 -1707.43,4998.8 -1747.95,5039.32 cw(c-1743.95,5043.32) -1747.95,5047.32 -1743.6,5051.67 -1740.16,5055.12 -1712.6,5055.12 -1692.81,5055.12 cw(c-1692.81,5049.46) -1687.15,5049.46 -1687.15,5044.78 ccw(c-1672.49,5044.78) -1672.49,5030.12 -1655.51,5030.12 ccw(c-1655.51,5044.78) -1640.85,5044.78 -1640.85,5074.46 cw(c-1635.19,5074.46) -1635.19,5080.12 -1618.21,5080.12 cw(c-1618.21,5074.46) -1612.55,5074.46 -1612.55,5044.78 ccw(c-1597.89,5044.78) -1597.89,5030.12 -1580.91,5030.12 ccw(c-1580.91,5044.78) -1566.25,5044.78 -1566.25,5074.46 cw(c-1560.59,5074.46) -1560.59,5080.12 -1543.61,5080.12 cw(c-1543.61,5074.46) -1537.95,5074.46 -1537.95,5044.78 ccw(c-1523.29,5044.78) -1523.29,5030.12 -1506.31,5030.12 ccw(c-1506.31,5044.78) -1491.65,5044.78 -1491.65,5074.46 cw(c-1485.99,5074.46) -1485.99,5080.12 -1469.01,5080.12 cw(c-1469.01,5074.46) -1463.35,5074.46 -1463.35,5044.78 ccw(c-1448.69,5044.78) -1448.69,5030.12 -1431.71,5030.12 ccw(c-1431.71,5044.78) -1417.05,5044.78 -1417.05,5074.46 cw(c-1411.39,5074.46) -1411.39,5080.12 -1394.41,5080.12 cw(c-1394.41,5074.46) -1388.75,5074.46 -1388.75,5044.78 ccw(c-1374.09,5044.78) -1374.09,5030.12 -1357.11,5030.12 ccw(c-1357.11,5044.78) -1342.45,5044.78 -1342.45,5049.46 cw(c-1336.79,5049.46) -1336.79,5055.12 -1330.64,5055.12 -1310.89,5055.12 -1044.45,5321.55 -868.7,5321.55 -845.87,5344.38 -845.87,5353.98 -843.94,5355.91 -840.97,5355.91 -834.62,5362.26 J6.34@-834.62,5399.01
PORTC_P2C_CLK_N: J6.35 MC3.47 | length 3385.6
  L1-TOP w3.3: MC3.47@-2293.31,3979.92 -2293.31,4002.56 -2298.65,4007.9 -2298.65,4023.92 -2298.65,4539.44 -2258.21,4579.87 -2237.04,4601.05 cw(c-2233.03,4597.05) -2229.03,4601.05 -2223.05,4595.07 ccw(c-2219.05,4599.07) -2215.05,4595.07 -2203.04,4607.07 ccw(c-2207.04,4611.08) -2203.04,4615.08 -2209.02,4621.06 cw(c-2205.02,4625.06) -2209.02,4629.06 -2190.7,4647.39 -2166.47,4671.61 -2155.16,4671.61 v1(-2153.54,4673.23)
  L6-BOT w3.3: v1(-2153.54,4673.23) -2151.93,4674.84 -2151.93,4686.16 -2144.01,4694.07 -2128.97,4709.12 ccw(c-2139.33,4719.49) -2128.97,4729.85 cw(c-2124.96,4733.85) -2128.97,4737.86 -2116.96,4749.86 cw(c-2112.96,4745.86) -2108.96,4749.86 -2107.47,4748.38 ccw(c-2097.09,4758.73) -2086.73,4748.37 -2074.72,4760.37 ccw(c-2085.09,4770.74) -2073.4,4779.59 -2073.4,4779.79 -2086.52,4792.91 -2113.4,4819.79 cw(c-2109.4,4823.79) -2113.4,4827.79 -2101.4,4839.8 cw(c-2097.39,4835.8) -2093.39,4839.8 -2054.72,4801.13 ccw(c-2044.34,4811.48) -2033.98,4801.12 -2021.97,4813.12 ccw(c-2032.34,4823.49) -2020.65,4832.34 -2020.65,4832.54 -2065.64,4877.53 cw(c-2061.64,4881.53) -2065.64,4885.54 -2053.64,4897.54 cw(c-2049.64,4893.54) -2045.63,4897.54 -2001.99,4853.89 ccw(c-1991.59,4864.23) -1981.23,4853.87 -1969.22,4865.87 ccw(c-1979.59,4876.24) -1967.9,4885.09 -1967.9,4885.29 -2012.89,4930.28 cw(c-2008.89,4934.28) -2012.89,4938.29 -2000.89,4950.29 cw(c-1996.89,4946.29) -1992.88,4950.29 -1949.23,4906.64 ccw(c-1938.84,4916.98) -1928.48,4906.62 -1916.47,4918.62 ccw(c-1926.84,4928.99) -1915.15,4937.84 -1915.15,4938.04 -1960.14,4983.03 cw(c-1956.14,4987.03) -1960.14,4991.04 -1948.14,5003.04 cw(c-1944.14,4999.04) -1940.13,5003.04 -1896.48,4959.39 ccw(c-1886.09,4969.73) -1875.73,4959.37 -1863.72,4971.37 ccw(c-1874.08,4981.74) -1862.4,4990.59 -1862.4,4990.79 -1907.39,5035.78 cw(c-1903.39,5039.78) -1907.39,5043.79 -1895.39,5055.79 cw(c-1891.39,5051.79) -1887.38,5055.79 -1843.73,5012.14 ccw(c-1833.34,5022.48) -1822.98,5012.12 -1810.97,5024.12 ccw(c-1821.33,5034.49) -1809.65,5043.34 -1809.65,5043.54 -1854.64,5088.53 cw(c-1850.64,5092.53) -1854.64,5096.54 -1842.64,5108.54 cw(c-1838.63,5104.54) -1834.63,5108.54 -1792.48,5066.39 ccw(c-1782.09,5076.73) -1771.72,5066.36 -1741,5097.09 -1502.31,5335.77 -1238.11,5335.77 -1011.43,5562.44 -920.56,5562.44 -887.13,5595.88 -856.9,5595.88 -854.97,5593.95 -854.97,5590.54 -862.01,5583.5 v2(-862.01,5581.25)
PORTC_P2C_CLK_P: J6.33 MC3.45 | length 3385.6
  L1-TOP w3.3: MC3.45@-2312.99,3979.92 -2312.99,4002.56 -2307.65,4007.9 -2307.65,4027.65 -2307.65,4543.16 -2172.84,4677.98 -2172.84,4689.29 v1(-2171.22,4690.91)
  L6-BOT w3.3: v1(-2171.22,4690.91) -2169.61,4692.52 -2158.29,4692.52 -2150.38,4700.44 -2135.33,4715.48 ccw(c-2139.33,4719.49) -2135.33,4723.49 cw(c-2124.96,4733.85) -2135.33,4744.22 -2123.32,4756.23 cw(c-2112.96,4745.86) -2102.59,4756.23 -2101.55,4755.19 -2101.09,4754.73 ccw(c-2097.09,4758.73) -2093.09,4754.73 -2081.08,4766.74 ccw(c-2085.09,4770.74) -2081.09,4774.75 ; -2081.11,4774.77 -2119.77,4813.42 cw(c-2109.4,4823.79) -2119.77,4834.16 -2107.76,4846.16 cw(c-2097.39,4835.8) -2087.03,4846.16 -2060.15,4819.28 -2048.34,4807.48 ccw(c-2044.34,4811.48) -2040.34,4807.48 -2028.33,4819.49 ccw(c-2032.34,4823.49) -2028.34,4827.5 ; -2028.36,4827.52 -2071.98,4871.14 cw(c-2061.64,4881.53) -2072.01,4891.9 -2060,4903.91 cw(c-2049.64,4893.54) -2040.78,4905.22 -2040.59,4905.22 -1995.59,4860.23 ccw(c-1991.59,4864.23) -1987.59,4860.23 -1975.58,4872.24 ccw(c-1979.59,4876.24) -1975.59,4880.25 ; -1975.61,4880.27 -2019.23,4923.89 cw(c-2008.89,4934.28) -2019.26,4944.65 -2007.25,4956.66 cw(c-1996.89,4946.29) -1988.03,4957.97 -1987.84,4957.97 -1942.84,4912.98 ccw(c-1938.84,4916.98) -1934.84,4912.98 -1922.83,4924.99 ccw(c-1926.84,4928.99) -1922.84,4933 ; -1922.86,4933.02 -1966.48,4976.64 cw(c-1956.14,4987.03) -1966.51,4997.4 -1954.5,5009.41 cw(c-1944.14,4999.04) -1935.28,5010.72 -1935.09,5010.72 -1890.09,4965.73 ccw(c-1886.09,4969.73) -1882.09,4965.73 -1870.08,4977.74 ccw(c-1874.08,4981.74) -1870.09,4985.75 ; -1870.11,4985.77 -1913.73,5029.39 cw(c-1903.39,5039.78) -1913.76,5050.15 -1901.75,5062.16 cw(c-1891.39,5051.79) -1882.53,5063.47 -1882.34,5063.47 -1837.34,5018.48 ccw(c-1833.34,5022.48) -1829.34,5018.48 -1817.33,5030.49 ccw(c-1821.33,5034.49) -1817.34,5038.5 ; -1817.36,5038.52 -1860.98,5082.14 cw(c-1850.64,5092.53) -1861.01,5102.9 -1849,5114.91 cw(c-1838.63,5104.54) -1829.78,5116.22 -1829.59,5116.22 -1786.09,5072.73 ccw(c-1782.09,5076.73) -1778.09,5072.73 -1747.36,5103.45 -1506.04,5344.77 -1241.84,5344.77 -1015.16,5571.44 -924.29,5571.44 -890.85,5604.88 -853.18,5604.88 -845.97,5597.67 -845.97,5590.54 -838.94,5583.5 v2(-838.94,5581.25)
PORTC_S0_D0_P: J6.5 MC3.58 | length 3384
  L1-TOP w3.3: MC3.58@-2194.88,3736.61 -2194.88,3713.98 -2189.54,3708.63 -2189.54,3694.59 -2176.18,3681.23 -2128.39,3681.23 -2120.39,3673.23 v1(-2118.11,3673.23)
  L6-BOT w3.3: v1(-2118.11,3673.23) -2115.83,3673.23 -2107.83,3681.23 -2040.67,3681.23 -1984.76,3737.14 -1984.76,4061.57 -1870.29,4176.04 -1844.93,4176.04 -1835.2,4185.77 -1830.85,4190.12 ccw(c-1841.22,4200.48) -1829.53,4209.34 -1829.53,4209.53 -1830.83,4210.83 ; -1830.85,4210.85 -1847.44,4227.44 cw(c-1843.43,4231.44) -1847.44,4235.44 -1835.43,4247.45 cw(c-1831.43,4243.44) -1827.41,4247.44 ; -1827.4,4247.42 -1793.19,4213.21 ccw(c-1782.8,4223.55) -1772.43,4213.18 -1760.39,4225.23 ccw(c-1770.79,4235.56) -1759.1,4244.41 -1759.1,4244.6 -1769.51,4255.01 -1790.19,4275.69 cw(c-1786.19,4279.69) -1790.19,4283.7 -1778.18,4295.7 cw(c-1774.18,4291.7) -1770.18,4295.7 -1758.09,4283.61 ccw(c-1747.72,4293.98) -1737.36,4283.61 -1687.37,4333.6 -1679.39,4341.58 -1679.39,4438.72 -1637.56,4480.55 -1534.28,4480.55 -1027.56,4987.27 -1027.56,5093.87 -981.95,5139.48 -570.61,5139.48 -383.66,5326.43 -383.66,5582.85 -404.87,5604.07 -404.87,5658.69 -397.84,5665.72 v2(-397.84,5667.97)
PORTC_S1_D1_P: J6.6 MC3.61 | length 3566.6
  L1-TOP w3.3: MC3.61@-1958.66,3979.92 -1958.66,4002.56 -1953.32,4007.9 -1953.32,4029.71 -1973.05,4049.45 -1973.05,4233.21 -1947.62,4258.65 -1638.75,4567.51 cw(c-1628.39,4557.15) -1619.53,4568.83 -1619.34,4568.83 -1618.04,4567.53 -1610.56,4560.05 -1593.57,4543.06 ccw(c-1589.57,4547.06) -1585.56,4543.06 -1573.56,4555.07 ccw(c-1577.56,4559.07) -1573.56,4563.07 -1615.66,4605.18 cw(c-1605.32,4615.57) -1615.69,4625.93 -1603.65,4637.98 cw(c-1593.32,4627.58) -1584.46,4639.26 -1584.27,4639.26 -1528.81,4583.8 ccw(c-1524.81,4587.81) -1520.81,4583.81 -1508.8,4595.81 ccw(c-1512.81,4599.82) -1508.82,4603.83 ; -1508.83,4603.85 -1562.91,4657.92 cw(c-1552.57,4668.32) -1562.94,4678.68 -1550.9,4690.73 cw(c-1540.57,4680.33) -1531.71,4692.01 -1531.52,4692.01 -1476.06,4636.55 ccw(c-1472.06,4640.56) -1468.06,4636.56 -1456.05,4648.56 ccw(c-1460.06,4652.57) -1456.07,4656.58 ; -1456.08,4656.6 -1510.16,4710.67 cw(c-1499.82,4721.07) -1510.19,4731.43 -1498.15,4743.48 cw(c-1487.82,4733.08) -1478.96,4744.76 -1478.77,4744.76 -1423.31,4689.3 ccw(c-1419.31,4693.31) -1415.31,4689.31 -1403.3,4701.31 ccw(c-1407.31,4705.32) -1403.32,4709.33 ; -1403.33,4709.35 -1457.41,4763.42 cw(c-1447.07,4773.82) -1457.44,4784.18 -1445.4,4796.23 cw(c-1435.07,4785.83) -1426.21,4797.51 -1426.02,4797.51 -1370.56,4742.05 ccw(c-1366.56,4746.06) -1362.56,4742.06 -1350.55,4754.06 ccw(c-1354.56,4758.07) -1350.57,4762.08 ; -1350.58,4762.1 -1387.01,4798.53 cw(c-1376.64,4808.89) -1387.01,4819.26 -1382.66,4823.61 -1002.78,5203.49 -350.04,5203.49 -282.34,5271.19 -282.34,5311.02 -282.34,5312.67 ccw(c-288,5312.67) -288,5318.33 -296.45,5318.33 cw(c-296.45,5323.99) -302.11,5323.99 -302.11,5340.97 cw(c-296.45,5340.97) -296.45,5346.63 -288,5346.63 ccw(c-288,5352.29) -282.34,5352.29 -282.34,5366.14 -282.34,5433.54 -307.18,5458.38 -394,5458.38 -404.87,5447.51 -404.87,5444.04 -402.94,5442.11 -399.97,5442.11 -393.62,5435.76 J6.6@-393.62,5399.01
PORTC_S2_D0_N: J6.7 MC3.60 | length 3383.9
  L1-TOP w3.3: MC3.60@-2175.2,3736.61 -2175.2,3713.98 -2180.54,3708.63 -2180.54,3698.32 -2172.45,3690.23 -2128.39,3690.23 -2120.39,3698.23 v1(-2118.11,3698.23)
  L6-BOT w3.3: v1(-2118.11,3698.23) -2115.83,3698.23 -2107.83,3690.23 -2044.4,3690.23 -1993.76,3740.87 -1993.76,3762.04 -1993.76,3763.69 ccw(c-1999.42,3763.69) -1999.42,3769.35 -2007.87,3769.35 cw(c-2007.87,3775.01) -2013.53,3775.01 -2013.53,3791.99 cw(c-2007.87,3791.99) -2007.87,3797.65 -1999.42,3797.65 ccw(c-1999.42,3803.31) -1993.76,3803.31 -1993.76,3842.65 -1993.76,4065.29 -1874.02,4185.04 -1848.66,4185.04 -1841.56,4192.13 -1837.21,4196.48 ccw(c-1841.22,4200.48) -1837.23,4204.5 -1853.77,4221.04 cw(c-1843.43,4231.44) -1853.8,4241.8 -1841.76,4253.85 cw(c-1831.43,4243.44) -1822.57,4255.13 -1822.38,4255.13 -1786.79,4219.54 ccw(c-1782.8,4223.55) -1778.79,4219.55 -1766.79,4231.55 ccw(c-1770.79,4235.56) -1766.8,4239.57 ; -1766.81,4239.58 -1796.56,4269.33 cw(c-1786.19,4279.69) -1796.56,4290.06 -1784.51,4302.1 cw(c-1774.18,4291.7) -1763.82,4302.07 -1751.73,4289.98 ccw(c-1747.72,4293.98) -1743.72,4289.98 -1693.73,4339.96 -1688.39,4345.31 -1688.39,4442.45 -1641.29,4489.55 -1538.01,4489.55 -1036.56,4991 -1036.56,5097.6 -985.68,5148.48 -574.34,5148.48 -392.66,5330.16 -392.66,5579.13 -413.87,5600.34 -413.87,5658.69 -420.91,5665.72 v2(-420.91,5667.97)
PORTC_S3_D1_N: J6.8 MC3.63 | length 3566.5
  L1-TOP w3.3: MC3.63@-1938.98,3979.92 -1938.98,4002.56 -1944.32,4007.9 -1944.32,4033.44 -1964.05,4053.18 -1964.05,4229.49 -1941.26,4252.28 -1632.39,4561.15 cw(c-1628.39,4557.15) -1624.37,4561.13 -1599.93,4536.7 ccw(c-1589.57,4547.06) -1579.2,4536.7 -1567.16,4548.74 ccw(c-1577.56,4559.07) -1567.19,4569.44 -1596.47,4598.71 -1609.33,4611.57 cw(c-1605.32,4615.57) -1609.32,4619.57 -1597.32,4631.58 cw(c-1593.32,4627.58) -1589.3,4631.57 ; -1589.28,4631.55 -1535.21,4577.47 ccw(c-1524.81,4587.81) -1514.45,4577.44 -1502.4,4589.49 ccw(c-1512.81,4599.82) -1501.12,4608.67 -1501.12,4608.86 -1556.58,4664.32 cw(c-1552.57,4668.32) -1556.57,4672.32 -1544.57,4684.33 cw(c-1540.57,4680.33) -1536.55,4684.32 ; -1536.53,4684.3 -1482.46,4630.22 ccw(c-1472.06,4640.56) -1461.7,4630.19 -1449.65,4642.24 ccw(c-1460.06,4652.57) -1448.37,4661.42 -1448.37,4661.61 -1503.83,4717.07 cw(c-1499.82,4721.07) -1503.82,4725.07 -1491.82,4737.08 cw(c-1487.82,4733.08) -1483.8,4737.07 ; -1483.78,4737.05 -1429.71,4682.97 ccw(c-1419.31,4693.31) -1408.95,4682.94 -1396.9,4694.99 ccw(c-1407.31,4705.32) -1395.62,4714.17 -1395.62,4714.36 -1451.08,4769.82 cw(c-1447.07,4773.82) -1451.07,4777.82 -1439.07,4789.83 cw(c-1435.07,4785.83) -1431.05,4789.82 ; -1431.03,4789.8 -1376.96,4735.72 ccw(c-1366.56,4746.06) -1356.2,4735.69 -1344.15,4747.74 ccw(c-1354.56,4758.07) -1342.87,4766.92 -1342.87,4767.11 -1380.65,4804.89 cw(c-1376.64,4808.89) -1380.65,4812.89 -1376.3,4817.24 -999.05,5194.49 -346.31,5194.49 -273.34,5267.46 -273.34,5437.26 -303.45,5467.38 -397.73,5467.38 -413.87,5451.24 -413.87,5444.04 -415.8,5442.11 -418.77,5442.11 -425.12,5435.76 J6.8@-425.12,5399.01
